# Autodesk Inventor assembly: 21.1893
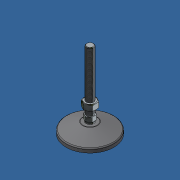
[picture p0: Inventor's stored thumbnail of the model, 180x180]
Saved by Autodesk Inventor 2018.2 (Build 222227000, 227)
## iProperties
Created: 2007-03
Part Number: 21.1893
Document SubType Name: Assembly
Designer: Andy Moles
Description: LEVELING FOOT M12 80mm BASE
Mass: 240.717 g
Surface Area: 316.697 cm^2
Volume: 88.2203 cm^3
Density: 2.7286 g/cm^3
Author: Andy Moles
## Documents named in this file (5)
- Y:\INVENTOR LIBRARIES\PARTS LIBRARY\FEET WHEELS FLOOR FASTENING SUPPORTS\21.1893 LEVELING FOOT M12 80mm BASE.iam
- Y:\INVENTOR LIBRARIES\PARTS LIBRARY\FASTENING ELEMENTS\NUTS\21.1528 M12 HEX NUT.ipt
- Y:\INVENTOR LIBRARIES\PARTS LIBRARY\FEET WHEELS FLOOR FASTENING SUPPORTS\SUBCOMPONENTS\LEVELING FEET SUBCOMPONENTS\PAD 80mm PLASTIC.ipt
- Y:\INVENTOR LIBRARIES\PARTS LIBRARY\FEET WHEELS FLOOR FASTENING SUPPORTS\SUBCOMPONENTS\LEVELING FEET SUBCOMPONENTS\ANTI-SKID PAD 80mm.ipt
- Y:\INVENTOR LIBRARIES\PARTS LIBRARY\FEET WHEELS FLOOR FASTENING SUPPORTS\SUBCOMPONENTS\LEVELING FEET SUBCOMPONENTS\THREADED STUD 12mm 100mm THREAD.ipt
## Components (4 placed, 4 different names)
1. ANTI-SKID PAD 80mm:1 — Insert:1
2. PAD 80mm PLASTIC:1 — Insert:1, Tangent:1, Mate:1
3. THREADED STUD 12mm 100mm THREAD:1 — Tangent:1, Mate:1, Mate:2
4. 21.1528 M12 HEX NUT:1 — Mate:2
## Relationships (4: Mate 2, Insert 1, Tangent 1)
- Insert:1: ANTI-SKID PAD 80mm:1 ↔ PAD 80mm PLASTIC:1
- Tangent:1: PAD 80mm PLASTIC:1 ↔ THREADED STUD 12mm 100mm THREAD:1
- Mate:1: PAD 80mm PLASTIC:1 ↔ THREADED STUD 12mm 100mm THREAD:1
- Mate:2: THREADED STUD 12mm 100mm THREAD:1 ↔ 21.1528 M12 HEX NUT:1
